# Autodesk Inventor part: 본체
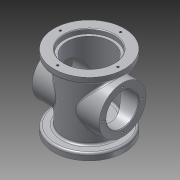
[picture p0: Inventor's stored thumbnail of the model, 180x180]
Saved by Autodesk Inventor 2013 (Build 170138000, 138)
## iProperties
Created: 2018-02
Part Number: 본체
Material: 알루미늄 6061
Document SubType Name: Modeling
Designer: Administrator
Density: 2.71 g/cm^3
Mass: 759.257 g
Surface Area: 822.557 cm^2
Volume: 280.169 cm^3
Author: Administrator
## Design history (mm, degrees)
sketch "스케치1"
  geometry: C1 r 38 at (0, 0); 1 further point
  constraints: 1 centre point, 1 coincident
  dimensions: "d0" = 76 diameter of C1
extrude "돌출1" new body sketch "스케치1" stored distance "d1" = 108; taper "d2" = 0 deg
sketch "스케치2"
  geometry: C1 r 38 at (0, 0) reference; C2 r 52.5 at (0, 0)
  constraints: 1 centre point, 1 coincident
  dimensions: "d3" = 105 diameter of C2
extrude "돌출2" join sketch "스케치2" distance "d4" = 10; taper "d5" = 0 deg
sketch "스케치3"
  geometry: C1 r 52.5 at (0, 0) reference; C2 r 33 at (0, 0)
  constraints: 1 centre point, 1 coincident
  dimensions: "d6" = 66 diameter of C2
extrude "돌출3" cut sketch "스케치3" distance "d7" = 86; taper "d8" = 0 deg
sketch "스케치4"
  geometry: C1 r 33 at (0, 0) reference; C2 r 52.5 at (0, 0) reference; C3 r 37 at (0, 0)
  constraints: 1 centre point, 1 coincident
  dimensions: "d9" = 74 diameter of C3
extrude "돌출4" cut sketch "스케치4" distance "d10" = 7; taper "d11" = 0 deg
chamfer "모따기1" distance "d12" = 1; stored, may be unused: second distance "d13" = 2, angle "d14" = 45 deg
sketch "스케치5"
  geometry: C1 r 52.5 at (0, 0) reference; C2 r 34 at (0, 0)
  constraints: 1 centre point, 1 coincident
  dimensions: "d15" = 68 diameter of C2
extrude "돌출5" cut sketch "스케치5" distance "d17" = 16; taper "d18" = 0 deg
sketch "스케치6"
  geometry: C1 r 34 at (0, 0) reference; C2 r 5 at (0, 0)
  constraints: 1 centre point, 1 coincident
  dimensions: "d19" = 10 diameter of C2
extrude "돌출6" cut sketch "스케치6" distance "d20" = 36.5; taper "d21" = 0 deg
node "작업 평면2"
sketch "스케치7"
  geometry: C1 r 35 at (0, 0); 1 further point
  constraints: 1 centre point, 1 coincident
  dimensions: "d23" = 70 diameter of C1
extrude "돌출7" join sketch "스케치7" stored distance "d24" = 36.5; taper "d25" = 0 deg
sketch "스케치8"
  geometry: C1 r 35 at (0, 0) reference; C2 r 24 at (0, 0)
  constraints: 1 centre point, 1 coincident
  dimensions: "d26" = 48 diameter of C2
extrude "돌출8" cut sketch "스케치8" distance "d27" = 133.75; taper "d28" = 0 deg
sketch "스케치9" dims "d29" = 58
  geometry: C1 r 24 at (0, 0) reference; 2 further points
  constraints: 1 coincident, 1 horizontal alignment, 2 other
hole "구멍1" sketch "스케치9" at (-29, 0) diameter "d30" = 3.242; stored, may be unused: countersink angle "d34" = 90 deg, drill point angle "d36" = 118 deg; dims "d31" = 4, "d32" = 4, "d33" = 2, "d35" = 6
sketch "스케치10" dims "d40" = 90
  geometry: C1 r 52.5 at (0, 0) reference; 2 further points
  constraints: 1 coincident, 3 other
hole "구멍2" sketch "스케치10" at (1.966, 44.957) diameter "d41" = 3.242; stored, may be unused: countersink angle "d45" = 90 deg, drill point angle "d47" = 118 deg; dims "d42" = 4, "d43" = 4, "d44" = 2, "d46" = 6
chamfer "모따기2" distance "d51" = 1; stored, may be unused: second distance "d52" = 2, angle "d53" = 45 deg
fillet "모깎기3" dims "d80" = 3
fillet "모깎기4" dims "d81" = 3
fillet "모깎기5" dims "d82" = 3
node "작업 평면6"
sketch "스케치23"
  geometry: L1 (-7, 13)-(7, 13); L2 (7, 13)-(7, -13); L3 (7, -13)-(-7, -13); L4 (-7, -13)-(-7, 13); C1 r 7 at (0, 13); 4 further points
  constraints: 8 end point, 4 midpoint, 2 horizontal alignment, 2 parallel, 2 tangent, 1 centre point, 1 horizontal, 1 perpendicular, 1 vertical, 1 vertical alignment, 2 other
  dimensions: "d102" = 14 diameter of C1; "d105" = 13 distance of point (0, -13) point (0, 0)
node "작업 평면7"
node "작업 평면9"
sketch "스케치38"
  geometry: 1 further point
sketch "스케치39"
  geometry: 1 further point
extrude "돌출19" join sketch "스케치23" stored distance "d150" = 14; taper "d151" = 0 deg
sketch "스케치40"
  geometry: A1 r 7 centre (0, -13) between (-7, -13) and (7, -13) reference; A2 r 7 centre (0, 13) between (7, 13) and (-7, 13) reference; 3 further points
  constraints: 2 coincident
hole "구멍7" sketch "스케치40" at (0, -13), (0, 13) diameter "d159" = 4.134; stored, may be unused: countersink angle "d163" = 90 deg, drill point angle "d165" = 118 deg; dims "d160" = 6, "d161" = 4, "d162" = 2, "d164" = 8
node "솔리드1"
mirror "대칭1"
mirror "대칭2"
pattern_circular "원형 패턴1" dims angle "d38" = 360 deg
mirror "대칭3"
pattern_circular "원형 패턴2" dims angle "d49" = 360 deg
other parameters: "d101" = 55
